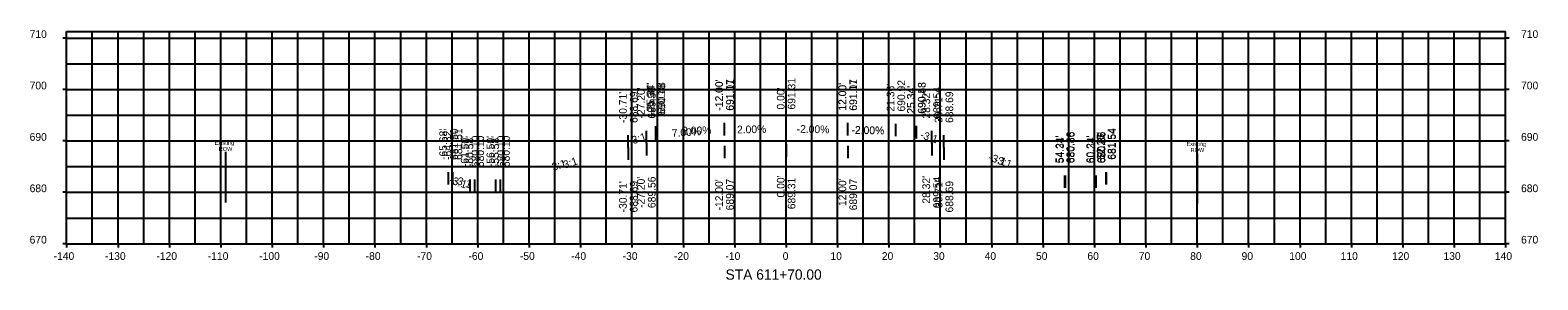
# Model space of a CAD drawing. Extents: x -147 to 146, y 663 to 712.
import ezdxf

# ---------------------------------------------------------------- set-up
doc = ezdxf.new("R2010")
doc.units = 0
for name, color, linetype in [('Contours Major', 7, 'Continuous'), ('Contours Minor', 7, 'Continuous'), ('Draft_3', 7, 'Continuous'), ('EXT_CON', 7, 'Continuous'), ('EXT_SNP', 7, 'Continuous'), ('Terrain', 7, 'Continuous')]:
    doc.layers.add(name, color=color, linetype=linetype)

msp = doc.modelspace()

# ---------------------------------------------------------------- linework, layer by layer
at = {"layer": 'Contours Major'}
for p, q in [((-135, 670), (-135, 711.31)), ((-125, 670), (-125, 711.31)), ((-115, 670), (-115, 711.31)), ((-105, 670), (-105, 711.31)), ((-95, 670), (-95, 711.31)), ((-85, 670), (-85, 711.31)), ((-75, 670), (-75, 711.31)), ((-65, 670), (-65, 711.31)), ((-55, 670), (-55, 711.31)), ((-45, 670), (-45, 711.31)), ((-35, 670), (-35, 711.31)), ((-25, 670), (-25, 711.31)), ((-15, 670), (-15, 711.31)), ((-5, 670), (-5, 711.31)), ((5, 670), (5, 711.31)), ((15, 670), (15, 711.31)), ((25, 670), (25, 711.31)), ((35, 670), (35, 711.31)), ((45, 670), (45, 711.31)), ((55, 670), (55, 711.31)), ((65, 670), (65, 711.31)), ((75, 670), (75, 711.31)), ((85, 670), (85, 711.31)), ((95, 670), (95, 711.31)), ((105, 670), (105, 711.31)), ((115, 670), (115, 711.31)), ((125, 670), (125, 711.31)), ((135, 670), (135, 711.31)), ((-140, 705), (140, 705)), ((-140, 695), (140, 695)), ((-140, 685), (140, 685)), ((-140, 675), (140, 675))]:
    msp.add_line(p, q, dxfattribs=at)
at = {"layer": 'Contours Minor'}
for p, q in [((-140, 710), (-140.72, 710)), ((-140, 710), (140, 710)), ((-130, 670), (-130, 711.31)), ((-120, 670), (-120, 711.31)), ((-110, 670), (-110, 711.31)), ((-100, 670), (-100, 711.31)), ((-90, 670), (-90, 711.31)), ((-80, 670), (-80, 711.31)), ((-70, 670), (-70, 711.31)), ((-60, 670), (-60, 711.31)), ((-50, 670), (-50, 711.31)), ((-40, 670), (-40, 711.31)), ((-30, 670), (-30, 711.31)), ((-20, 670), (-20, 711.31)), ((-10, 670), (-10, 711.31)), ((0, 670), (0, 711.31)), ((10, 670), (10, 711.31)), ((20, 670), (20, 711.31)), ((30, 670), (30, 711.31)), ((40, 670), (40, 711.31)), ((50, 670), (50, 711.31)), ((60, 670), (60, 711.31)), ((70, 670), (70, 711.31)), ((80, 670), (80, 711.31)), ((90, 670), (90, 711.31)), ((100, 670), (100, 711.31)), ((110, 670), (110, 711.31)), ((120, 670), (120, 711.31)), ((130, 670), (130, 711.31)), ((140.72, 710), (140, 710)), ((-140, 700), (-140.72, 700)), ((-140, 700), (140, 700)), ((140.72, 700), (140, 700)), ((-140, 690), (-140.72, 690)), ((-140, 690), (140, 690)), ((140.72, 690), (140, 690)), ((-140, 680), (-140.72, 680)), ((-140, 680), (140, 680)), ((140.72, 680), (140, 680)), ((-140, 670), (-140.72, 670)), ((-140, 670), (-140, 669.28)), ((-130, 670), (-130, 669.28)), ((-120, 670), (-120, 669.28)), ((-110, 670), (-110, 669.28)), ((-100, 670), (-100, 669.28)), ((-90, 670), (-90, 669.28)), ((-80, 670), (-80, 669.28)), ((-70, 670), (-70, 669.28)), ((-60, 670), (-60, 669.28)), ((-50, 670), (-50, 669.28)), ((-40, 670), (-40, 669.28)), ((-30, 670), (-30, 669.28)), ((-20, 670), (-20, 669.28)), ((-10, 670), (-10, 669.28)), ((0, 670), (0, 669.28)), ((10, 670), (10, 669.28)), ((20, 670), (20, 669.28)), ((30, 670), (30, 669.28)), ((40, 670), (40, 669.28)), ((50, 670), (50, 669.28)), ((60, 670), (60, 669.28)), ((70, 670), (70, 669.28)), ((80, 670), (80, 669.28)), ((90, 670), (90, 669.28)), ((100, 670), (100, 669.28)), ((110, 670), (110, 669.28)), ((120, 670), (120, 669.28)), ((130, 670), (130, 669.28)), ((140, 670), (140, 669.28)), ((140.72, 670), (140, 670))]:
    msp.add_line(p, q, dxfattribs=at)
at = {"layer": 'EXT_CON'}
for p, q in [((-109.1, 687.88), (-109.1, 678.03)), ((80, 687.67), (80, 677.83))]:
    msp.add_line(p, q, dxfattribs=at)
at = {"layer": 'EXT_SNP'}
for p, q in [((-25.34, 690.48), (-25.34, 692.88)), ((-25.34, 690.18), (-25.34, 692.58)), ((-12, 691.11), (-12, 693.51)), ((-12, 691.07), (-12, 693.47)), ((0, 691.31), (0, 693.71)), ((12, 691.11), (12, 693.51)), ((12, 691.07), (12, 693.47)), ((21.36, 690.92), (21.36, 693.32)), ((25.34, 690.53), (25.34, 692.93)), ((25.34, 690.48), (25.34, 692.88)), ((-30.71, 688.69), (-30.71, 691.09)), ((-27.2, 689.56), (-27.2, 691.96)), ((-27.2, 689.56), (-27.2, 687.16)), ((28.32, 689.54), (28.32, 691.94)), ((28.32, 689.54), (28.32, 691.94)), ((28.32, 689.54), (28.32, 687.14)), ((30.71, 688.69), (30.71, 691.09)), ((30.71, 688.69), (30.71, 691.09)), ((-30.71, 688.69), (-30.71, 686.29)), ((-12, 689.07), (-12, 686.67)), ((0, 689.31), (0, 686.91)), ((12, 689.07), (12, 686.67)), ((30.71, 688.69), (30.71, 686.29)), ((-65.68, 681.5), (-65.68, 683.9)), ((-64.82, 681.51), (-64.82, 683.91)), ((62.25, 681.54), (62.25, 683.94)), ((62.37, 681.54), (62.37, 683.94)), ((-61.5, 680.1), (-61.5, 682.5)), ((-60.58, 680.1), (-60.58, 682.5)), ((-56.5, 680.1), (-56.5, 682.5)), ((-55.58, 680.1), (-55.58, 682.5)), ((54.21, 680.86), (54.21, 683.26)), ((54.34, 680.86), (54.34, 683.26)), ((60.21, 680.86), (60.21, 683.26)), ((60.34, 680.86), (60.34, 683.26))]:
    msp.add_line(p, q, dxfattribs=at)
at = {"layer": 'Terrain'}
for p, q in [((-140, 711.31), (140, 711.31)), ((-140, 670), (-140, 711.31)), ((140, 670), (140, 711.31)), ((-140, 670), (140, 670))]:
    msp.add_line(p, q, dxfattribs=at)

# ---------------------------------------------------------------- texts
at = {"layer": 'Draft_3'}
for s, height, p in [('710', 1.5, (-147.2, 710.03)), ('710', 1.5, (143, 710.03)), ('700', 1.5, (-147.2, 700.03)), ('700', 1.5, (143, 700.03)), ('690', 1.5, (-147.2, 690.03)), ('690', 1.5, (143, 690.03)), ('680', 1.5, (-147.2, 680.03)), ('680', 1.5, (143, 680.03)), ('670', 1.5, (-147.2, 670.03)), ('670', 1.5, (143, 670.03)), ('-140', 1.5, (-142.53, 666.85)), ('-130', 1.5, (-132.53, 666.85)), ('-120', 1.5, (-122.53, 666.85)), ('-110', 1.5, (-112.53, 666.85)), ('-100', 1.5, (-102.53, 666.85)), ('-90', 1.5, (-91.81, 666.85)), ('-80', 1.5, (-81.81, 666.85)), ('-70', 1.5, (-71.81, 666.85)), ('-60', 1.5, (-61.81, 666.85)), ('-50', 1.5, (-51.81, 666.85)), ('-40', 1.5, (-41.81, 666.85)), ('-30', 1.5, (-31.81, 666.85)), ('-20', 1.5, (-21.81, 666.85)), ('-10', 1.5, (-11.81, 666.85)), ('0', 1.5, (-0.67, 666.85)), ('10', 1.5, (8.62, 666.85)), ('20', 1.5, (18.62, 666.85)), ('30', 1.5, (28.62, 666.85)), ('40', 1.5, (38.62, 666.85)), ('50', 1.5, (48.62, 666.85)), ('60', 1.5, (58.62, 666.85)), ('70', 1.5, (68.62, 666.85)), ('80', 1.5, (78.62, 666.85)), ('90', 1.5, (88.62, 666.85)), ('100', 1.5, (97.9, 666.85)), ('110', 1.5, (107.9, 666.85)), ('120', 1.5, (117.9, 666.85)), ('130', 1.5, (127.9, 666.85)), ('140', 1.5, (137.9, 666.85)), ('STA 611+70.00', 2.004, (-11.78, 663))]:
    msp.add_text(s, height=height, dxfattribs=at).set_placement(p)
at = {"layer": 'EXT_CON'}
for s, p in [('Existing', (-111.19, 689.23)), ('Existing', (77.91, 689.02)), ('ROW', (-110.41, 688.05)), ('ROW', (78.69, 687.84))]:
    msp.add_text(s, height=0.787, dxfattribs=at).set_placement(p)
at = {"layer": 'EXT_SNP'}
for s, rotation, p in [("-25.34'", 90, (-25.64, 695.28)), ('690.48', 90, (-23.54, 695.28)), ("-12.00'", 90, (-12.3, 695.91)), ("-12.00'", 90, (-12.3, 695.87)), ('691.11', 90, (-10.2, 695.91)), ('691.07', 90, (-10.2, 695.87)), ('691.31', 90, (1.8, 696.11)), ("12.00'", 90, (11.7, 695.91)), ("12.00'", 90, (11.7, 695.87)), ('691.11', 90, (13.8, 695.91)), ('691.07', 90, (13.8, 695.87)), ('690.92', 90, (23.16, 695.72)), ('690.53', 90, (27.14, 695.33)), ('690.48', 90, (27.14, 695.28)), ("-30.71'", 90, (-31.01, 693.49)), ('688.69', 90, (-28.91, 693.49)), ("-27.20'", 90, (-27.5, 694.36)), ("-25.34'", 90, (-25.64, 694.98)), ('689.56', 90, (-25.4, 694.36)), ('690.18', 90, (-23.54, 694.98)), ("0.00'", 90, (-0.3, 696.11)), ("21.36'", 90, (21.06, 695.72)), ("25.34'", 90, (25.04, 695.33)), ("25.34'", 90, (25.04, 695.28)), ("28.32'", 90, (28.02, 694.34)), ("28.32'", 90, (28.02, 694.34)), ('689.54', 90, (30.12, 694.34)), ('689.54', 90, (30.12, 694.34)), ("30.71'", 90, (30.41, 693.49)), ("30.71'", 90, (30.41, 693.49)), ('688.69', 90, (32.51, 693.49)), ('688.69', 90, (32.51, 693.49)), ('681.50', 90, (-63.88, 686.3)), ('681.51', 90, (-63.02, 686.31)), ('7.00%', 4.0057, (-22.2, 690.73)), ('2.00%', 1.1458, (-20.22, 691.23)), ('2.00%', 1.1458, (-9.54, 691.45)), ('-2.00%', 358.8542, (2.04, 691.6)), ('-2.00%', 358.8542, (12.72, 691.43)), ('-2.00%', 358.8542, (12.72, 691.38)), ('681.54', 90, (64.05, 686.34)), ('681.54', 90, (64.17, 686.34)), ("-65.68'", 90, (-65.98, 686.3)), ("-64.82'", 90, (-65.12, 686.31)), ("-61.50'", 90, (-61.8, 684.9)), ("-60.58'", 90, (-60.88, 684.9)), ('680.10', 90, (-59.7, 684.9)), ('680.10', 90, (-58.78, 684.9)), ("-56.50'", 90, (-56.8, 684.9)), ("-55.58'", 90, (-55.88, 684.9)), ('680.10', 90, (-54.7, 684.9)), ('680.10', 90, (-53.78, 684.9)), ('3:1', 18.4332, (-29.72, 689.36)), ('-3:1', 341.5668, (25.95, 690.61)), ("54.21'", 90, (53.91, 685.66)), ("54.34'", 90, (54.04, 685.66)), ('680.86', 90, (56.01, 685.66)), ('680.86', 90, (56.14, 685.66)), ("60.21'", 90, (59.91, 685.66)), ("60.34'", 90, (60.04, 685.66)), ("62.25'", 90, (61.95, 686.34)), ('680.86', 90, (62.01, 685.66)), ("62.37'", 90, (62.07, 686.34)), ('680.86', 90, (62.14, 685.66)), ('3:1', 18.4332, (-43.08, 684.6)), ('-3:1', 341.5668, (39.25, 686.22)), ('-3:1', 341.5668, (40.38, 685.8)), ('3:1', 18.4332, (-45.29, 684.16)), ('-3:1', 341.5668, (-65.67, 681.82)), ('-3:1', 341.5668, (-64.78, 681.83)), ("-30.71'", 90, (-31.01, 676.1)), ('688.69', 90, (-28.91, 676.08)), ("-27.20'", 90, (-27.5, 676.96)), ('689.56', 90, (-25.4, 676.93)), ("-12.00'", 90, (-12.3, 676.47)), ('689.07', 90, (-10.2, 676.49)), ("0.00'", 90, (-0.3, 679)), ('689.31', 90, (1.8, 676.71)), ("12.00'", 90, (11.7, 677.32)), ('689.07', 90, (13.8, 676.49)), ("28.32'", 90, (28.02, 677.79)), ('689.54', 90, (30.12, 676.89)), ("30.71'", 90, (30.41, 676.95)), ('688.69', 90, (32.51, 676.08))]:
    msp.add_text(s, height=1.5, rotation=rotation, dxfattribs=at).set_placement(p)

doc.saveas('drawing.dxf')
